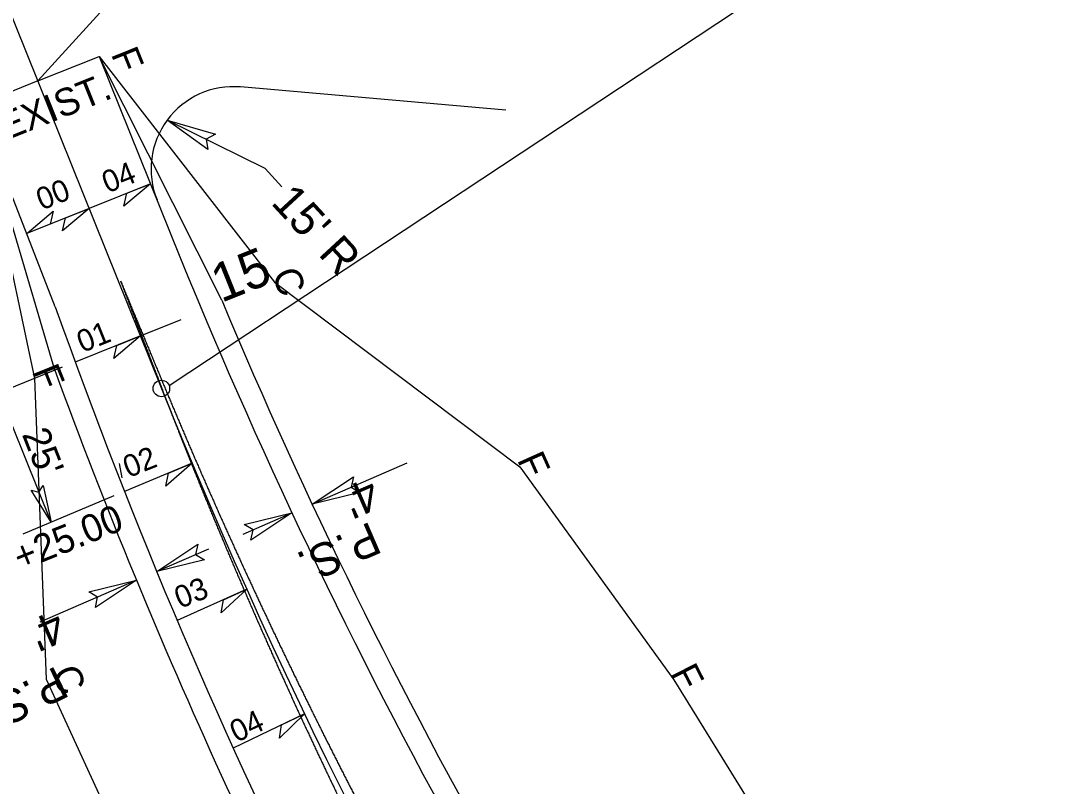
# Model space of a CAD drawing. Extents: x 1702862 to 1704514, y 793768 to 796215.
# Drawn here: x 1703028 to 1703216.2, y 795553 to 795692.3 of the extents above; entities that cross this region are included whole.
import ezdxf

# ---------------------------------------------------------------- set-up
doc = ezdxf.new("R2010")
doc.units = 0
for name, color, linetype in [('Default', 7, 'Continuous'), ('Prop Dimension', 7, 'Continuous'), ('Prop DSN Text', 7, 'Continuous'), ('Prop EOT', 7, 'Continuous'), ('Prop Horizontal Alignment', 7, 'Continuous'), ('Prop Horizontal Alignment Station Label', 7, 'Continuous'), ('Prop Horizontal Alignment Tick Label', 7, 'Continuous'), ('Prop Horizontal Alignment Tick Large', 7, 'Continuous'), ('Prop Lane Lines', 7, 'Continuous'), ('Prop Leader Line Medium', 7, 'Continuous'), ('Prop Paint Stripe', 7, 'Continuous'), ('Prop Paved Shoulder', 7, 'Continuous'), ('Prop SS Cut Line', 7, 'Continuous'), ('Prop SS Fill Line', 7, 'Continuous'), ('Prop SS Misc', 7, 'Continuous'), ('Prop SS Transition Line', 7, 'Continuous'), ('Prop Superelevation  Arrow CELL', 7, 'Continuous'), ('Prop Superelevation Label', 7, 'Continuous'), ('Prop Terminator CELL', 7, 'Continuous')]:
    doc.layers.add(name, color=color, linetype=linetype)

msp = doc.modelspace()

# ---------------------------------------------------------------- linework, layer by layer
at = {"layer": 'Default'}
msp.add_line((1703046.41, 795609.2), (1703045.95, 795611.75), dxfattribs=at)
at = {"layer": 'Prop Dimension'}
for p, q in [((1703080.99, 795604.39), (1703098.29, 795611.88)), ((1703068.44, 795598.95), (1703077.32, 795602.8)), ((1703062.1, 795596.21), (1703052.71, 795592.14)), ((1703049.04, 795590.55), (1703031.47, 795582.94))]:
    msp.add_line(p, q, dxfattribs=at)
msp.add_lwpolyline([(1703075.5, 795662.14), (1703072.46, 795665.44), (1703054.61, 795674.26)], dxfattribs=at)
at = {"layer": 'Prop EOT'}
for p, q in [((1703031.09, 795681.38), (1703042.22, 795685.85)), ((1703042.22, 795685.85), (1703056.94, 795649.37)), ((1703031.09, 795681.38), (1703019.95, 795676.91)), ((1703116.2, 795676.08), (1703067.97, 795680.28)), ((1703034.25, 795640.31), (1703019.95, 795676.91))]:
    msp.add_line(p, q, dxfattribs=at)
for centre, radius, start, end in [((1703066.67, 795665.34), 15, 85.025, 201.9624), ((1703979.03, 796025.18), 995.74, 202.1738, 216.36225), ((1703995.36, 795980.89), 1019.67, 199.51266, 213.76578)]:
    msp.add_arc(centre, radius, start, end, dxfattribs=at)
at = {"layer": 'Prop Horizontal Alignment'}
msp.add_line((1702863.33, 796098.94), (1703053.56, 795625.43), dxfattribs=at)
msp.add_arc((1703981.48, 795998.22), 1000, 201.8874, 222.70907, dxfattribs=at)
at = {"layer": 'Prop Horizontal Alignment Station Label'}
msp.add_line((1703054.96, 795625.99), (1703206.95, 795726.48), dxfattribs=at)
msp.add_circle((1703053.56, 795625.43), 1.5, dxfattribs=at)
at = {"layer": 'Prop Horizontal Alignment Tick Large'}
msp.add_line((1703049.73, 795634.98), (1703057.15, 795637.97), dxfattribs=at)
at = {"layer": 'Prop Lane Lines'}
for points in [[(1703046.1, 795645.04), (1703046.44, 795644.24), (1703046.77, 795643.44), (1703047.1, 795642.63), (1703047.44, 795641.83), (1703047.77, 795641.03), (1703048.1, 795640.23), (1703048.44, 795639.42), (1703048.77, 795638.62), (1703049.1, 795637.82), (1703049.43, 795637.02), (1703049.77, 795636.21), (1703050.1, 795635.41), (1703050.43, 795634.61), (1703050.77, 795633.81), (1703051.1, 795633), (1703051.43, 795632.2), (1703051.77, 795631.4), (1703052.1, 795630.6), (1703052.43, 795629.79), (1703052.76, 795628.99), (1703053.1, 795628.19), (1703053.43, 795627.39), (1703053.76, 795626.58), (1703054.1, 795625.78), (1703054.43, 795624.98), (1703054.77, 795624.18), (1703055.1, 795623.38), (1703055.44, 795622.58), (1703055.77, 795621.78), (1703056.11, 795620.98), (1703056.45, 795620.18), (1703056.79, 795619.38), (1703057.13, 795618.58), (1703057.47, 795617.78), (1703057.81, 795616.98), (1703058.15, 795616.18), (1703058.49, 795615.38), (1703058.84, 795614.58), (1703059.18, 795613.79), (1703059.52, 795612.99), (1703059.87, 795612.19), (1703060.22, 795611.4), (1703060.56, 795610.6), (1703060.91, 795609.8), (1703061.26, 795609.01), (1703061.61, 795608.21), (1703061.95, 795607.42), (1703062.3, 795606.62), (1703062.65, 795605.83), (1703063.01, 795605.04), (1703063.36, 795604.24), (1703063.71, 795603.45), (1703064.06, 795602.65), (1703064.42, 795601.86), (1703064.77, 795601.07), (1703065.13, 795600.28), (1703065.48, 795599.49), (1703065.84, 795598.69), (1703066.2, 795597.9), (1703066.56, 795597.11), (1703066.91, 795596.32), (1703067.27, 795595.53), (1703067.63, 795594.74), (1703068, 795593.95), (1703068.36, 795593.16), (1703068.72, 795592.37), (1703069.08, 795591.58), (1703069.45, 795590.8), (1703069.81, 795590.01), (1703070.17, 795589.22), (1703070.54, 795588.43), (1703070.91, 795587.65), (1703071.27, 795586.86), (1703071.64, 795586.07)], [(1703046.1, 795645.04), (1703046.42, 795644.23), (1703046.73, 795643.42), (1703047.04, 795642.61), (1703047.35, 795641.8), (1703047.66, 795640.98), (1703047.97, 795640.17), (1703048.28, 795639.36), (1703048.6, 795638.55), (1703048.91, 795637.74), (1703049.22, 795636.93), (1703049.53, 795636.12), (1703049.84, 795635.31), (1703050.15, 795634.5), (1703050.47, 795633.69), (1703050.78, 795632.87), (1703051.09, 795632.06), (1703051.4, 795631.25), (1703051.71, 795630.44), (1703052.02, 795629.63), (1703052.33, 795628.82), (1703052.65, 795628.01), (1703052.96, 795627.2), (1703053.27, 795626.39), (1703053.58, 795625.58), (1703053.89, 795624.76), (1703054.21, 795623.95), (1703054.52, 795623.14), (1703054.84, 795622.33), (1703055.15, 795621.52), (1703055.47, 795620.71), (1703055.78, 795619.9), (1703056.1, 795619.1), (1703056.42, 795618.29), (1703056.74, 795617.48), (1703057.06, 795616.67), (1703057.38, 795615.86), (1703057.7, 795615.05), (1703058.02, 795614.25), (1703058.35, 795613.44), (1703058.67, 795612.63), (1703058.99, 795611.83), (1703059.32, 795611.02), (1703059.64, 795610.21), (1703059.97, 795609.41), (1703060.3, 795608.6), (1703060.62, 795607.8), (1703060.95, 795606.99), (1703061.28, 795606.19), (1703061.61, 795605.38), (1703061.94, 795604.58), (1703062.27, 795603.78), (1703062.6, 795602.97), (1703062.94, 795602.17), (1703063.27, 795601.37), (1703063.6, 795600.56), (1703063.94, 795599.76), (1703064.27, 795598.96), (1703064.61, 795598.16), (1703064.95, 795597.36), (1703065.28, 795596.55), (1703065.62, 795595.75), (1703065.96, 795594.95), (1703066.3, 795594.15), (1703066.64, 795593.35), (1703066.98, 795592.55), (1703067.32, 795591.75), (1703067.66, 795590.95), (1703068.01, 795590.15), (1703068.35, 795589.36), (1703068.69, 795588.56), (1703069.04, 795587.76), (1703069.39, 795586.96), (1703069.73, 795586.16), (1703070.08, 795585.37)], [(1703070.08, 795585.37), (1703070.43, 795584.57), (1703070.78, 795583.77), (1703071.12, 795582.98), (1703071.47, 795582.18), (1703071.83, 795581.39), (1703072.18, 795580.59), (1703072.53, 795579.79), (1703072.88, 795579), (1703073.23, 795578.2), (1703073.59, 795577.41), (1703073.94, 795576.62), (1703074.3, 795575.82), (1703074.65, 795575.03), (1703075.01, 795574.24), (1703075.37, 795573.44), (1703075.73, 795572.65), (1703076.09, 795571.86), (1703076.45, 795571.07), (1703076.81, 795570.28), (1703077.17, 795569.48), (1703077.53, 795568.69), (1703077.89, 795567.9), (1703078.25, 795567.11), (1703078.62, 795566.32), (1703078.98, 795565.53), (1703079.35, 795564.74), (1703079.71, 795563.95), (1703080.08, 795563.16), (1703080.45, 795562.38), (1703080.82, 795561.59), (1703081.18, 795560.8), (1703081.55, 795560.01), (1703081.92, 795559.23), (1703082.29, 795558.44), (1703082.67, 795557.65), (1703083.04, 795556.87), (1703083.41, 795556.08), (1703083.78, 795555.29), (1703084.16, 795554.51), (1703084.53, 795553.72), (1703084.91, 795552.94), (1703085.28, 795552.15), (1703085.66, 795551.37), (1703086.04, 795550.59), (1703086.42, 795549.8), (1703086.8, 795549.02), (1703087.18, 795548.24), (1703087.56, 795547.45), (1703087.94, 795546.67), (1703088.32, 795545.89), (1703088.7, 795545.11), (1703089.08, 795544.33), (1703089.47, 795543.55), (1703089.85, 795542.77), (1703090.24, 795541.99), (1703090.62, 795541.21), (1703091.01, 795540.43), (1703091.4, 795539.65), (1703091.78, 795538.87), (1703092.17, 795538.09), (1703092.56, 795537.31), (1703092.95, 795536.53), (1703093.34, 795535.76), (1703093.73, 795534.98), (1703094.12, 795534.2), (1703094.52, 795533.42), (1703094.91, 795532.65), (1703095.3, 795531.87), (1703095.7, 795531.1), (1703096.09, 795530.32), (1703096.49, 795529.55), (1703096.89, 795528.77), (1703097.28, 795528), (1703097.68, 795527.22)], [(1703071.64, 795586.07), (1703072.01, 795585.29), (1703072.38, 795584.5), (1703072.75, 795583.72), (1703073.12, 795582.93), (1703073.49, 795582.15), (1703073.86, 795581.36), (1703074.23, 795580.58), (1703074.61, 795579.79), (1703074.98, 795579.01), (1703075.35, 795578.23), (1703075.73, 795577.44), (1703076.11, 795576.66), (1703076.48, 795575.88), (1703076.86, 795575.1), (1703077.24, 795574.32), (1703077.62, 795573.54), (1703077.99, 795572.76), (1703078.37, 795571.97), (1703078.75, 795571.19), (1703079.14, 795570.42), (1703079.52, 795569.64), (1703079.9, 795568.86), (1703080.28, 795568.08), (1703080.67, 795567.3), (1703081.05, 795566.52), (1703081.44, 795565.74), (1703081.82, 795564.97), (1703082.21, 795564.19), (1703082.6, 795563.41), (1703082.98, 795562.64), (1703083.37, 795561.86), (1703083.76, 795561.09), (1703084.15, 795560.31), (1703084.54, 795559.54), (1703084.93, 795558.76), (1703085.33, 795557.99), (1703085.72, 795557.21), (1703086.11, 795556.44), (1703086.51, 795555.67), (1703086.9, 795554.89), (1703087.3, 795554.12), (1703087.69, 795553.35), (1703088.09, 795552.58), (1703088.48, 795551.81), (1703088.88, 795551.04), (1703089.28, 795550.26), (1703089.68, 795549.49), (1703090.08, 795548.72), (1703090.48, 795547.95), (1703090.88, 795547.19), (1703091.28, 795546.42), (1703091.69, 795545.65), (1703092.09, 795544.88), (1703092.49, 795544.11), (1703092.9, 795543.34), (1703093.3, 795542.58), (1703093.71, 795541.81), (1703094.12, 795541.04), (1703094.52, 795540.28), (1703094.93, 795539.51), (1703095.34, 795538.75), (1703095.75, 795537.98), (1703096.16, 795537.22), (1703096.57, 795536.45), (1703096.98, 795535.69), (1703097.39, 795534.93), (1703097.8, 795534.16), (1703098.22, 795533.4), (1703098.63, 795532.64), (1703099.05, 795531.88), (1703099.46, 795531.12), (1703099.88, 795530.35), (1703100.29, 795529.59), (1703100.71, 795528.83)]]:
    msp.add_spline(points, degree=3, dxfattribs=at)
at = {"layer": 'Prop Leader Line Medium'}
msp.add_line((1703176.52, 795841.48), (1703031.09, 795681.38), dxfattribs=at)
at = {"layer": 'Prop Paint Stripe'}
for points in [[(1703046.1, 795645.04), (1703046.44, 795644.24), (1703046.77, 795643.44), (1703047.1, 795642.63), (1703047.44, 795641.83), (1703047.77, 795641.03), (1703048.1, 795640.23), (1703048.44, 795639.42), (1703048.77, 795638.62), (1703049.1, 795637.82), (1703049.43, 795637.02), (1703049.77, 795636.21), (1703050.1, 795635.41), (1703050.43, 795634.61), (1703050.77, 795633.81), (1703051.1, 795633), (1703051.43, 795632.2), (1703051.77, 795631.4), (1703052.1, 795630.6), (1703052.43, 795629.79), (1703052.76, 795628.99), (1703053.1, 795628.19), (1703053.43, 795627.39), (1703053.76, 795626.58), (1703054.1, 795625.78), (1703054.43, 795624.98), (1703054.77, 795624.18), (1703055.1, 795623.38), (1703055.44, 795622.58), (1703055.77, 795621.78), (1703056.11, 795620.98), (1703056.45, 795620.18), (1703056.79, 795619.38), (1703057.13, 795618.58), (1703057.47, 795617.78), (1703057.81, 795616.98), (1703058.15, 795616.18), (1703058.49, 795615.38), (1703058.84, 795614.58), (1703059.18, 795613.79), (1703059.52, 795612.99), (1703059.87, 795612.19), (1703060.22, 795611.4), (1703060.56, 795610.6), (1703060.91, 795609.8), (1703061.26, 795609.01), (1703061.61, 795608.21), (1703061.95, 795607.42), (1703062.3, 795606.62), (1703062.65, 795605.83), (1703063.01, 795605.04), (1703063.36, 795604.24), (1703063.71, 795603.45), (1703064.06, 795602.65), (1703064.42, 795601.86), (1703064.77, 795601.07), (1703065.13, 795600.28), (1703065.48, 795599.49), (1703065.84, 795598.69), (1703066.2, 795597.9), (1703066.56, 795597.11), (1703066.91, 795596.32), (1703067.27, 795595.53), (1703067.63, 795594.74), (1703068, 795593.95), (1703068.36, 795593.16), (1703068.72, 795592.37), (1703069.08, 795591.58), (1703069.45, 795590.8), (1703069.81, 795590.01), (1703070.17, 795589.22), (1703070.54, 795588.43), (1703070.91, 795587.65), (1703071.27, 795586.86), (1703071.64, 795586.07)], [(1703046.1, 795645.04), (1703046.42, 795644.23), (1703046.73, 795643.42), (1703047.04, 795642.61), (1703047.35, 795641.8), (1703047.66, 795640.98), (1703047.97, 795640.17), (1703048.28, 795639.36), (1703048.6, 795638.55), (1703048.91, 795637.74), (1703049.22, 795636.93), (1703049.53, 795636.12), (1703049.84, 795635.31), (1703050.15, 795634.5), (1703050.47, 795633.69), (1703050.78, 795632.87), (1703051.09, 795632.06), (1703051.4, 795631.25), (1703051.71, 795630.44), (1703052.02, 795629.63), (1703052.33, 795628.82), (1703052.65, 795628.01), (1703052.96, 795627.2), (1703053.27, 795626.39), (1703053.58, 795625.58), (1703053.89, 795624.76), (1703054.21, 795623.95), (1703054.52, 795623.14), (1703054.84, 795622.33), (1703055.15, 795621.52), (1703055.47, 795620.71), (1703055.78, 795619.9), (1703056.1, 795619.1), (1703056.42, 795618.29), (1703056.74, 795617.48), (1703057.06, 795616.67), (1703057.38, 795615.86), (1703057.7, 795615.05), (1703058.02, 795614.25), (1703058.35, 795613.44), (1703058.67, 795612.63), (1703058.99, 795611.83), (1703059.32, 795611.02), (1703059.64, 795610.21), (1703059.97, 795609.41), (1703060.3, 795608.6), (1703060.62, 795607.8), (1703060.95, 795606.99), (1703061.28, 795606.19), (1703061.61, 795605.38), (1703061.94, 795604.58), (1703062.27, 795603.78), (1703062.6, 795602.97), (1703062.94, 795602.17), (1703063.27, 795601.37), (1703063.6, 795600.56), (1703063.94, 795599.76), (1703064.27, 795598.96), (1703064.61, 795598.16), (1703064.95, 795597.36), (1703065.28, 795596.55), (1703065.62, 795595.75), (1703065.96, 795594.95), (1703066.3, 795594.15), (1703066.64, 795593.35), (1703066.98, 795592.55), (1703067.32, 795591.75), (1703067.66, 795590.95), (1703068.01, 795590.15), (1703068.35, 795589.36), (1703068.69, 795588.56), (1703069.04, 795587.76), (1703069.39, 795586.96), (1703069.73, 795586.16), (1703070.08, 795585.37)], [(1703070.08, 795585.37), (1703070.43, 795584.57), (1703070.78, 795583.77), (1703071.12, 795582.98), (1703071.47, 795582.18), (1703071.83, 795581.39), (1703072.18, 795580.59), (1703072.53, 795579.79), (1703072.88, 795579), (1703073.23, 795578.2), (1703073.59, 795577.41), (1703073.94, 795576.62), (1703074.3, 795575.82), (1703074.65, 795575.03), (1703075.01, 795574.24), (1703075.37, 795573.44), (1703075.73, 795572.65), (1703076.09, 795571.86), (1703076.45, 795571.07), (1703076.81, 795570.28), (1703077.17, 795569.48), (1703077.53, 795568.69), (1703077.89, 795567.9), (1703078.25, 795567.11), (1703078.62, 795566.32), (1703078.98, 795565.53), (1703079.35, 795564.74), (1703079.71, 795563.95), (1703080.08, 795563.16), (1703080.45, 795562.38), (1703080.82, 795561.59), (1703081.18, 795560.8), (1703081.55, 795560.01), (1703081.92, 795559.23), (1703082.29, 795558.44), (1703082.67, 795557.65), (1703083.04, 795556.87), (1703083.41, 795556.08), (1703083.78, 795555.29), (1703084.16, 795554.51), (1703084.53, 795553.72), (1703084.91, 795552.94), (1703085.28, 795552.15), (1703085.66, 795551.37), (1703086.04, 795550.59), (1703086.42, 795549.8), (1703086.8, 795549.02), (1703087.18, 795548.24), (1703087.56, 795547.45), (1703087.94, 795546.67), (1703088.32, 795545.89), (1703088.7, 795545.11), (1703089.08, 795544.33), (1703089.47, 795543.55), (1703089.85, 795542.77), (1703090.24, 795541.99), (1703090.62, 795541.21), (1703091.01, 795540.43), (1703091.4, 795539.65), (1703091.78, 795538.87), (1703092.17, 795538.09), (1703092.56, 795537.31), (1703092.95, 795536.53), (1703093.34, 795535.76), (1703093.73, 795534.98), (1703094.12, 795534.2), (1703094.52, 795533.42), (1703094.91, 795532.65), (1703095.3, 795531.87), (1703095.7, 795531.1), (1703096.09, 795530.32), (1703096.49, 795529.55), (1703096.89, 795528.77), (1703097.28, 795528), (1703097.68, 795527.22)], [(1703071.64, 795586.07), (1703072.01, 795585.29), (1703072.38, 795584.5), (1703072.75, 795583.72), (1703073.12, 795582.93), (1703073.49, 795582.15), (1703073.86, 795581.36), (1703074.23, 795580.58), (1703074.61, 795579.79), (1703074.98, 795579.01), (1703075.35, 795578.23), (1703075.73, 795577.44), (1703076.11, 795576.66), (1703076.48, 795575.88), (1703076.86, 795575.1), (1703077.24, 795574.32), (1703077.62, 795573.54), (1703077.99, 795572.76), (1703078.37, 795571.97), (1703078.75, 795571.19), (1703079.14, 795570.42), (1703079.52, 795569.64), (1703079.9, 795568.86), (1703080.28, 795568.08), (1703080.67, 795567.3), (1703081.05, 795566.52), (1703081.44, 795565.74), (1703081.82, 795564.97), (1703082.21, 795564.19), (1703082.6, 795563.41), (1703082.98, 795562.64), (1703083.37, 795561.86), (1703083.76, 795561.09), (1703084.15, 795560.31), (1703084.54, 795559.54), (1703084.93, 795558.76), (1703085.33, 795557.99), (1703085.72, 795557.21), (1703086.11, 795556.44), (1703086.51, 795555.67), (1703086.9, 795554.89), (1703087.3, 795554.12), (1703087.69, 795553.35), (1703088.09, 795552.58), (1703088.48, 795551.81), (1703088.88, 795551.04), (1703089.28, 795550.26), (1703089.68, 795549.49), (1703090.08, 795548.72), (1703090.48, 795547.95), (1703090.88, 795547.19), (1703091.28, 795546.42), (1703091.69, 795545.65), (1703092.09, 795544.88), (1703092.49, 795544.11), (1703092.9, 795543.34), (1703093.3, 795542.58), (1703093.71, 795541.81), (1703094.12, 795541.04), (1703094.52, 795540.28), (1703094.93, 795539.51), (1703095.34, 795538.75), (1703095.75, 795537.98), (1703096.16, 795537.22), (1703096.57, 795536.45), (1703096.98, 795535.69), (1703097.39, 795534.93), (1703097.8, 795534.16), (1703098.22, 795533.4), (1703098.63, 795532.64), (1703099.05, 795531.88), (1703099.46, 795531.12), (1703099.88, 795530.35), (1703100.29, 795529.59), (1703100.71, 795528.83)]]:
    msp.add_spline(points, degree=3, dxfattribs=at)
at = {"layer": 'Prop Paved Shoulder'}
for p, q in [((1703064.53, 795641.47), (1703042.22, 795685.85)), ((1703034.17, 795628.74), (1703019.95, 795676.91))]:
    msp.add_line(p, q, dxfattribs=at)
for centre, radius, start, end in [((1703979.03, 796025.18), 991.74, 202.76171, 216.36225), ((1703995.36, 795980.89), 1023.67, 200.12156, 209.03806)]:
    msp.add_arc(centre, radius, start, end, dxfattribs=at)
at = {"layer": 'Prop SS Cut Line'}
msp.add_line((1703032.62, 795572.53), (1703054.27, 795525.22), dxfattribs=at)
at = {"layer": 'Prop SS Fill Line'}
for p, q in [((1703042.22, 795685.85), (1703074.15, 795644.8)), ((1703019.95, 795676.91), (1703030.46, 795627.25)), ((1703118.79, 795611.19), (1703146.79, 795572.42)), ((1703146.79, 795572.42), (1703171.45, 795532.58))]:
    msp.add_line(p, q, dxfattribs=at)
at = {"layer": 'Prop SS Transition Line'}
for p, q in [((1703074.15, 795644.8), (1703118.79, 795611.19)), ((1703030.46, 795627.25), (1703032.62, 795572.53))]:
    msp.add_line(p, q, dxfattribs=at)
at = {"layer": 'Prop Superelevation  Arrow CELL'}
for p, q in [((1703051.57, 795662.67), (1703040.44, 795658.2)), ((1703040.41, 795658.18), (1703029.05, 795653.62)), ((1703049.73, 795634.98), (1703037.89, 795630.23)), ((1703059.15, 795611.83), (1703046.84, 795606.67)), ((1703069.09, 795588.89), (1703056.44, 795583.22)), ((1703079.61, 795566.21), (1703066.62, 795559.99))]:
    msp.add_line(p, q, dxfattribs=at)
for points in [[(1703051.57, 795662.67), (1703046.75, 795658.58), (1703047.28, 795660.94)], [(1703040.41, 795658.18), (1703035.58, 795654.09), (1703036.11, 795656.46)], [(1703029.05, 795653.62), (1703033.87, 795657.71), (1703033.34, 795655.35)], [(1703049.73, 795634.98), (1703044.9, 795630.89), (1703045.43, 795633.26)], [(1703059.15, 795611.83), (1703054.38, 795607.66), (1703054.88, 795610.04)], [(1703069.09, 795588.89), (1703064.44, 795584.61), (1703064.87, 795587)], [(1703079.61, 795566.21), (1703075.06, 795561.82), (1703075.44, 795564.22)]]:
    msp.add_lwpolyline(points, close=True, dxfattribs=at)
at = {"layer": 'Prop Superelevation Label'}
for p, q in [((1703035.53, 795629.28), (1703018.79, 795622.56)), ((1703033.5, 795601.08), (1703024.01, 795624.65)), ((1703044.93, 795605.87), (1703028.37, 795598.93))]:
    msp.add_line(p, q, dxfattribs=at)
msp.add_lwpolyline([(1703032.05, 795607.78), (1703033.5, 795601.08), (1703029.85, 795606.93), (1703031.28, 795606.58)], close=True, dxfattribs=at)
at = {"layer": 'Prop Terminator CELL'}
for points in [[(1703061.99, 795668.88), (1703054.61, 795674.26), (1703063.43, 795671.68), (1703061.69, 795670.76)], [(1703089.66, 795606.49), (1703080.99, 795604.39), (1703088.48, 795609.34), (1703088.07, 795607.46)], [(1703068.64, 795600.69), (1703077.32, 795602.8), (1703069.82, 795597.85), (1703070.23, 795599.73)], [(1703061.38, 795594.25), (1703052.71, 795592.14), (1703060.2, 795597.09), (1703059.79, 795595.21)], [(1703040.36, 795588.44), (1703049.04, 795590.55), (1703041.54, 795585.6), (1703041.95, 795587.48)]]:
    msp.add_lwpolyline(points, close=True, dxfattribs=at)

# ---------------------------------------------------------------- texts
at = {"layer": 'Prop Dimension'}
for s, rotation, p in [("15' R", 312.7091, (1703073.33, 795659.12)), ("4'", 203.4176, (1703091.55, 795609.46)), ('P.S.', 203.4176, (1703091.64, 795601.28)), ("4'", 203.4176, (1703034.42, 795585.32)), ('P.S.', 206.2405, (1703034.48, 795575.02))]:
    msp.add_text(s, height=6, rotation=rotation, dxfattribs=at).set_placement(p)
at = {"layer": 'Prop DSN Text'}
msp.add_text('EXIST.', height=5, rotation=21.7746, dxfattribs=at).set_placement((1703025.23, 795670.49))
at = {"layer": 'Prop Horizontal Alignment Tick Label'}
msp.add_text('15', height=7, rotation=21.8874, dxfattribs=at).set_placement((1703064.45, 795640.97))
at = {"layer": 'Prop SS Misc'}
for s, rotation, p in [('F', 291.8874, (1703044.33, 795686.28)), ('C', 291.8874, (1703073.58, 795646.22)), ('F', 291.8874, (1703029.93, 795628.56)), ('F', 294.1624, (1703118.21, 795612.48)), ('F', 297.0272, (1703146.15, 795573.69)), ('C', 294.1624, (1703033.51, 795573.7))]:
    msp.add_text(s, height=5, rotation=rotation, dxfattribs=at).set_placement(p)
at = {"layer": 'Prop Superelevation Label'}
for s, height, rotation, p in [('04', 4, 21.8874, (1703043.75, 795660.9)), ('00', 4, 21.8874, (1703031.79, 795657.79)), ('01', 4, 21.8874, (1703039.18, 795631.88)), ("25'", 5, 291.3752, (1703028.14, 795617.1)), ('02', 4, 21.8874, (1703047.58, 795609.11)), ('+25.00', 5, 21.8881, (1703027.89, 795592.17)), ('03', 4, 21.8874, (1703056.94, 795585.33)), ('04', 4, 25.5948, (1703067.24, 795560.94))]:
    msp.add_text(s, height=height, rotation=rotation, dxfattribs=at).set_placement(p)

doc.saveas('drawing.dxf')
